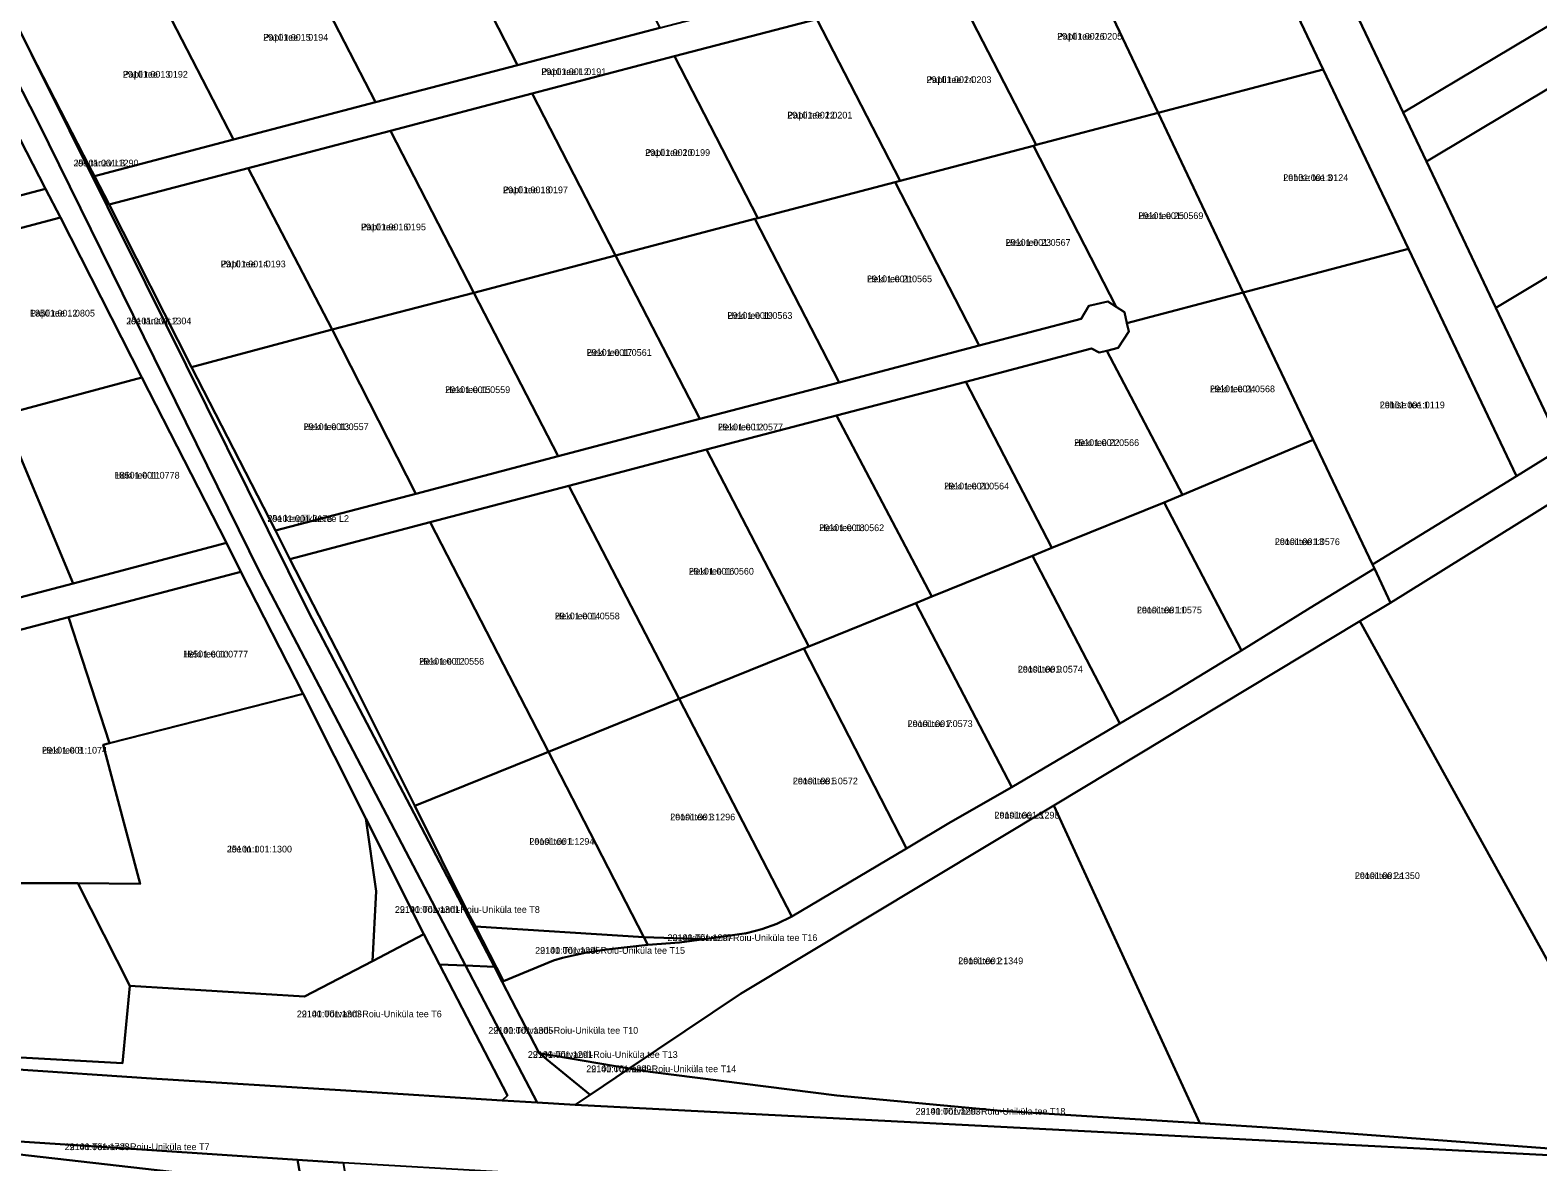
# Model space of a CAD drawing. Extents: x 660838 to 697091, y 6455678 to 6479886.
# Drawn here: x 664095.1 to 664431.6, y 6468197.9 to 6468450.3 of the extents above; entities that cross this region are included whole.
import ezdxf

# ---------------------------------------------------------------- set-up
doc = ezdxf.new("R2010")
doc.units = 0
for name, color, linetype in [('L_AADRESS', 7, 'Continuous'), ('PIIR', 7, 'Continuous'), ('TUNNUS', 7, 'Continuous')]:
    doc.layers.add(name, color=color, linetype=linetype)

msp = doc.modelspace()

# ---------------------------------------------------------------- linework, layer by layer
at = {"layer": 'PIIR'}
for points in [[(664313.61, 6468617.19), (664329.19, 6468584.39), (664334.36, 6468573.5), (664349.87, 6468540.83), (664365.38, 6468508.16), (664370.55, 6468497.27), (664386.06, 6468464.6), (664401.57, 6468431.93), (664406.74, 6468421.04), (664422.25, 6468388.37), (664437.07, 6468357.15), (664426.82, 6468350.79), (664402.72, 6468401.53), (664383.72, 6468441.55), (664365.17, 6468480.63), (664346.15, 6468520.69), (664326.53, 6468562.01), (664307.92, 6468601.21), (664288.66, 6468641.77)], [(664091.28, 6468218.5), (664122.2, 6468216.46), (664165.54, 6468213.74), (664200.48, 6468211.55), (664208.27, 6468211.09), (664216.77, 6468210.57), (664458.53, 6468198.06), (664579, 6468191.33), (664690.49, 6468185.61)], [(664729.07, 6468167.61), (664473.29, 6468181.55), (664464.58, 6468181.83), (664462.14, 6468181.96), (664413.82, 6468184.41), (664347.63, 6468187.75), (664236.55, 6468193.43), (664164.93, 6468197.64), (664154.73, 6468198.28), (664121.17, 6468200.49), (664090.44, 6468202.53)]]:
    msp.add_lwpolyline(points, dxfattribs=at)
for points in [[(664011.97, 6468594.44), (664010.85, 6468610.16), (664020.16, 6468591.48), (664045.52, 6468542.86), (664069.8, 6468495.5), (664072.61, 6468490.03), (664083.83, 6468468.15), (664091.12, 6468453.52), (664095.38, 6468444.97), (664120.83, 6468393.91), (664157.25, 6468320.55), (664198.71, 6468241.32), (664192.29, 6468241.62), (664146.38, 6468329.37), (664096.86, 6468429.82), (664045.92, 6468529.46), (664044.65, 6468529.2), (664044.72, 6468533.87), (664017.4, 6468586.35)], [(664406.74, 6468421.04), (664401.57, 6468431.93), (664442.44, 6468456.35), (664479.35, 6468478.41), (664519.73, 6468502.53), (664523.16, 6468504.58), (664566.08, 6468530.22), (664609.01, 6468555.87), (664651.92, 6468581.5), (664658.19, 6468571.28), (664613.54, 6468544.6), (664571.48, 6468519.47), (664529.41, 6468494.33), (664547.97, 6468463.93), (664565.51, 6468435.19), (664562.05, 6468433.18), (664544.54, 6468461.87), (664525.98, 6468492.28), (664485.63, 6468468.18), (664445.28, 6468444.07)], [(664061.69, 6468487.25), (664058.48, 6468493.66), (664040.86, 6468528.27), (664042.85, 6468528.78), (664044.65, 6468529.2), (664045.92, 6468529.46), (664096.86, 6468429.82), (664146.38, 6468329.37), (664192.29, 6468241.62), (664186.43, 6468241.89), (664182.99, 6468248.64), (664170.02, 6468274.46), (664156.03, 6468302.27), (664142.09, 6468329.5), (664138.93, 6468335.94), (664119.99, 6468372.84), (664101.86, 6468408.55), (664098.51, 6468414.91), (664082.82, 6468445.33), (664075.71, 6468459.37)], [(664398.73, 6468322.58), (664395.13, 6468330.21), (664394.74, 6468331.12), (664426.82, 6468350.79), (664437.07, 6468357.15), (664481.53, 6468384.67), (664521.71, 6468409.06), (664562.05, 6468433.18), (664565.51, 6468435.19), (664607.86, 6468459.86), (664650.34, 6468484.32), (664690.06, 6468507.49), (664700.43, 6468513.57), (664700.73, 6468512.97), (664584.64, 6468443.92), (664588.08, 6468438.22), (664559.82, 6468421.4), (664544.15, 6468411.97), (664487.89, 6468378.07)], [(664185.46, 6468478.38), (664217.17, 6468486.73), (664235.65, 6468450.87), (664203.9, 6468442.55)], [(664401.57, 6468431.93), (664386.06, 6468464.6), (664423.68, 6468487.09), (664442.44, 6468456.35)], [(664346.87, 6468431.87), (664328.13, 6468471.41), (664365.17, 6468480.63), (664383.72, 6468441.55)], [(664153.76, 6468470.03), (664185.46, 6468478.38), (664203.9, 6468442.55), (664172.21, 6468434.24)], [(664293.66, 6468467.54), (664297.73, 6468469.22), (664298.27, 6468468.99), (664301.79, 6468467.54), (664302.8, 6468465.1), (664303.48, 6468463.47), (664301.8, 6468459.42), (664297.73, 6468457.72), (664294.48, 6468459.06), (664270.67, 6468452.82), (664238.94, 6468444.5), (664207.18, 6468436.17), (664175.5, 6468427.87), (664143.75, 6468419.54), (664112.73, 6468411.41), (664109.42, 6468417.78), (664140.45, 6468425.92), (664172.21, 6468434.24), (664203.9, 6468442.55), (664235.65, 6468450.87), (664267.38, 6468459.19), (664292.77, 6468465.85)], [(664122.04, 6468461.69), (664153.76, 6468470.03), (664172.21, 6468434.24), (664140.45, 6468425.92)], [(664302.8, 6468465.1), (664328.13, 6468471.41), (664346.87, 6468431.87), (664319.63, 6468424.72), (664301.8, 6468459.42), (664303.48, 6468463.47)], [(664091.12, 6468453.52), (664122.04, 6468461.69), (664140.45, 6468425.92), (664109.42, 6468417.78), (664108.26, 6468419.99), (664095.38, 6468444.97)], [(664297.73, 6468457.72), (664301.8, 6468459.42), (664319.63, 6468424.72), (664319.03, 6468424.56), (664289.26, 6468416.74), (664270.67, 6468452.82), (664294.48, 6468459.06)], [(664238.94, 6468444.5), (664270.67, 6468452.82), (664289.26, 6468416.74), (664288.14, 6468416.45), (664257.52, 6468408.41)], [(664047.87, 6468442.82), (664071.93, 6468449.23), (664074.89, 6468442.69), (664082.82, 6468445.33), (664098.51, 6468414.91), (664064.26, 6468405.93)], [(664157.25, 6468320.55), (664120.83, 6468393.91), (664095.38, 6468444.97), (664108.26, 6468419.99), (664109.42, 6468417.78), (664112.73, 6468411.41), (664131.12, 6468375.17), (664149.86, 6468338.73), (664153.03, 6468332.3), (664165.97, 6468307.19), (664180.96, 6468277.24), (664192.82, 6468253.46), (664194.46, 6468250.34), (664200.77, 6468238.18), (664200.45, 6468238.01), (664198.71, 6468241.32)], [(664207.18, 6468436.17), (664238.94, 6468444.5), (664257.52, 6468408.41), (664256.84, 6468408.24), (664225.76, 6468400.06)], [(664422.25, 6468388.37), (664406.74, 6468421.04), (664445.28, 6468444.07), (664463.97, 6468413.44)], [(664365.86, 6468391.8), (664346.87, 6468431.87), (664383.72, 6468441.55), (664402.72, 6468401.53)], [(664175.5, 6468427.87), (664207.18, 6468436.17), (664225.76, 6468400.06), (664194.1, 6468391.73)], [(664319.63, 6468424.72), (664346.87, 6468431.87), (664365.86, 6468391.8), (664339.9, 6468384.98), (664339.35, 6468387.39), (664337.49, 6468388.61), (664319.03, 6468424.56)], [(664143.75, 6468419.54), (664175.5, 6468427.87), (664194.1, 6468391.73), (664162.54, 6468383.54)], [(664289.26, 6468416.74), (664319.03, 6468424.56), (664337.49, 6468388.61), (664335.65, 6468389.76), (664331.39, 6468388.82), (664329.65, 6468385.89), (664306.93, 6468379.95), (664288.14, 6468416.45)], [(664112.73, 6468411.41), (664143.75, 6468419.54), (664162.54, 6468383.54), (664131.12, 6468375.17)], [(664257.52, 6468408.41), (664288.14, 6468416.45), (664306.93, 6468379.95), (664275.69, 6468371.75), (664256.84, 6468408.24)], [(664098.51, 6468414.91), (664101.86, 6468408.55), (664070.12, 6468400.11), (664037.18, 6468391.48), (664004.69, 6468382.98), (663972.11, 6468374.47), (663939.71, 6468366), (663931.01, 6468363.73), (663930.12, 6468366.43), (663928.84, 6468370.43), (663935.15, 6468372.06), (663965.71, 6468380.05), (663998.2, 6468388.6), (664030.62, 6468397.11), (664064.26, 6468405.93)], [(664437.07, 6468357.15), (664422.25, 6468388.37), (664463.97, 6468413.44), (664481.53, 6468384.67)], [(664070.12, 6468400.11), (664101.86, 6468408.55), (664119.99, 6468372.84), (664088.98, 6468364.5), (664085.96, 6468363.69)], [(664225.76, 6468400.06), (664256.84, 6468408.24), (664275.69, 6468371.75), (664244.54, 6468363.58)], [(664194.1, 6468391.73), (664225.76, 6468400.06), (664244.54, 6468363.58), (664212.93, 6468355.27)], [(664394.74, 6468331.12), (664381.49, 6468358.94), (664365.86, 6468391.8), (664402.72, 6468401.53), (664426.82, 6468350.79)], [(664162.54, 6468383.54), (664194.1, 6468391.73), (664212.93, 6468355.27), (664181.16, 6468346.92)], [(664339.9, 6468384.98), (664365.86, 6468391.8), (664381.49, 6468358.94), (664352.28, 6468346.65), (664335.39, 6468378.8), (664337.97, 6468379.42), (664340.32, 6468383.1)], [(664331.39, 6468388.82), (664335.65, 6468389.76), (664337.49, 6468388.61), (664339.35, 6468387.39), (664339.9, 6468384.98), (664340.32, 6468383.1), (664337.97, 6468379.42), (664335.39, 6468378.8), (664333.68, 6468378.44), (664331.98, 6468379.3), (664303.94, 6468371.9), (664275.06, 6468364.35), (664246.09, 6468356.75), (664215.36, 6468348.7), (664184.41, 6468340.56), (664153.03, 6468332.3), (664149.86, 6468338.73), (664181.16, 6468346.92), (664212.93, 6468355.27), (664244.54, 6468363.58), (664275.69, 6468371.75), (664306.93, 6468379.95), (664329.65, 6468385.89)], [(664131.12, 6468375.17), (664162.54, 6468383.54), (664181.16, 6468346.92), (664149.86, 6468338.73)], [(664303.94, 6468371.9), (664331.98, 6468379.3), (664333.68, 6468378.44), (664335.39, 6468378.8), (664352.28, 6468346.65), (664348.18, 6468344.97), (664323.12, 6468334.82)], [(664487.89, 6468378.07), (664579, 6468191.33), (664458.53, 6468198.06), (664458.37, 6468198.35), (664457.98, 6468199.04), (664391.9, 6468318.48), (664398.73, 6468322.58)], [(664088.98, 6468364.5), (664119.99, 6468372.84), (664138.93, 6468335.94), (664104.7, 6468326.9)], [(664275.06, 6468364.35), (664303.94, 6468371.9), (664323.12, 6468334.82), (664318.82, 6468333.05), (664296.32, 6468323.97)], [(664056.43, 6468355.76), (664085.96, 6468363.69), (664088.98, 6468364.5), (664104.7, 6468326.9), (664071.43, 6468318.15)], [(664246.09, 6468356.75), (664275.06, 6468364.35), (664296.32, 6468323.97), (664292.78, 6468322.5), (664268.9, 6468312.84)], [(664352.28, 6468346.65), (664381.49, 6468358.94), (664394.74, 6468331.12), (664395.13, 6468330.21), (664380.78, 6468321.45), (664365.44, 6468311.96), (664348.18, 6468344.97)], [(664215.36, 6468348.7), (664246.09, 6468356.75), (664268.9, 6468312.84), (664267.76, 6468312.36), (664239.98, 6468301.13)], [(664184.41, 6468340.56), (664215.36, 6468348.7), (664239.98, 6468301.13), (664210.81, 6468289.33)], [(664323.12, 6468334.82), (664348.18, 6468344.97), (664365.44, 6468311.96), (664349.44, 6468302.21), (664338.32, 6468295.65), (664318.82, 6468333.05)], [(664153.03, 6468332.3), (664184.41, 6468340.56), (664210.81, 6468289.33), (664180.96, 6468277.24), (664165.97, 6468307.19)], [(664138.93, 6468335.94), (664142.09, 6468329.5), (664103.67, 6468319.4), (664075.84, 6468312.07), (664047.71, 6468304.7), (664018.32, 6468296.96), (663982.59, 6468287.6), (663964.77, 6468282.8), (663964.11, 6468284.71), (663962.55, 6468289.49), (663972.93, 6468292.22), (664005.47, 6468300.79), (664038.5, 6468309.59), (664071.43, 6468318.15), (664104.7, 6468326.9)], [(664296.32, 6468323.97), (664318.82, 6468333.05), (664338.32, 6468295.65), (664314.17, 6468281.47), (664292.78, 6468322.5)], [(664103.67, 6468319.4), (664142.09, 6468329.5), (664156.03, 6468302.27), (664112.78, 6468291.23)], [(664380.78, 6468321.45), (664395.13, 6468330.21), (664398.73, 6468322.58), (664391.9, 6468318.48), (664323.58, 6468277.38), (664253.65, 6468235.35), (664228.83, 6468218.67), (664208.74, 6468222.11), (664200.45, 6468238.01), (664200.77, 6468238.18), (664211.94, 6468242.79), (664213.9, 6468243.39), (664219.33, 6468244.54), (664223.71, 6468245.23), (664232.96, 6468246.28), (664240, 6468246.81), (664245.5, 6468247.56), (664255, 6468248.85), (664258.39, 6468249.78), (664261.78, 6468250.92), (664265.1, 6468252.62), (664290.71, 6468267.78), (664300.51, 6468273.6), (664314.17, 6468281.47), (664338.32, 6468295.65), (664349.44, 6468302.21), (664365.44, 6468311.96)], [(664268.9, 6468312.84), (664292.78, 6468322.5), (664314.17, 6468281.47), (664300.51, 6468273.6), (664290.71, 6468267.78), (664267.76, 6468312.36)], [(664075.84, 6468312.07), (664103.67, 6468319.4), (664112.78, 6468291.23), (664111.41, 6468290.88), (664119.66, 6468259.88), (664105.73, 6468259.99), (664090.17, 6468260.05)], [(664323.58, 6468277.38), (664391.9, 6468318.48), (664457.98, 6468199.04), (664374.67, 6468205.31), (664356.17, 6468206.5)], [(664239.98, 6468301.13), (664267.76, 6468312.36), (664290.71, 6468267.78), (664265.1, 6468252.62)], [(664112.78, 6468291.23), (664156.03, 6468302.27), (664170.02, 6468274.46), (664172.33, 6468258.27), (664171.5, 6468242.59), (664156.34, 6468234.74), (664117.34, 6468237.15), (664105.73, 6468259.99), (664119.66, 6468259.88), (664111.41, 6468290.88)], [(664210.81, 6468289.33), (664239.98, 6468301.13), (664265.1, 6468252.62), (664261.78, 6468250.92), (664258.39, 6468249.78), (664255, 6468248.85), (664245.5, 6468247.56), (664232.08, 6468247.94)], [(664117.34, 6468237.15), (664115.71, 6468219.88), (664059.46, 6468222.99), (663965.92, 6468232.47), (663944.79, 6468278.74), (663964.11, 6468284.71), (663964.77, 6468282.8), (663982.59, 6468287.6), (663992.24, 6468260.2), (664029.61, 6468260.17), (664060.31, 6468260.11), (664084.21, 6468260.09), (664090.17, 6468260.05), (664105.73, 6468259.99)], [(664194.46, 6468250.34), (664192.82, 6468253.46), (664180.96, 6468277.24), (664210.81, 6468289.33), (664232.08, 6468247.94)], [(664228.83, 6468218.67), (664253.65, 6468235.35), (664323.58, 6468277.38), (664356.17, 6468206.5), (664311.77, 6468209.25), (664275.11, 6468212.64), (664233.46, 6468217.91)], [(664172.33, 6468258.27), (664170.02, 6468274.46), (664182.99, 6468248.64), (664171.5, 6468242.59)], [(664200.77, 6468238.18), (664194.46, 6468250.34), (664232.08, 6468247.94), (664232.96, 6468246.28), (664223.71, 6468245.23), (664219.33, 6468244.54), (664213.9, 6468243.39), (664211.94, 6468242.79)], [(663965.79, 6468231.38), (663965.92, 6468232.47), (664059.46, 6468222.99), (664115.71, 6468219.88), (664117.34, 6468237.15), (664156.34, 6468234.74), (664171.5, 6468242.59), (664182.99, 6468248.64), (664186.43, 6468241.89), (664201.65, 6468212.63), (664200.48, 6468211.55), (664165.54, 6468213.74), (664122.2, 6468216.46), (664091.28, 6468218.5), (664074.07, 6468219.81), (664052.27, 6468221.67), (664031.71, 6468223.7), (664010.87, 6468226), (663986.88, 6468228.81)], [(664232.96, 6468246.28), (664232.08, 6468247.94), (664245.5, 6468247.56), (664240, 6468246.81)], [(664201.65, 6468212.63), (664186.43, 6468241.89), (664192.29, 6468241.62), (664208.27, 6468211.09), (664200.48, 6468211.55)], [(664208.27, 6468211.09), (664192.29, 6468241.62), (664198.71, 6468241.32), (664200.45, 6468238.01), (664208.74, 6468222.11), (664220.08, 6468212.77), (664216.77, 6468210.57)], [(664220.08, 6468212.77), (664208.74, 6468222.11), (664228.83, 6468218.67)], [(664458.53, 6468198.06), (664216.77, 6468210.57), (664220.08, 6468212.77), (664228.83, 6468218.67), (664233.46, 6468217.91), (664275.11, 6468212.64), (664311.77, 6468209.25), (664356.17, 6468206.5), (664374.67, 6468205.31), (664457.98, 6468199.04), (664458.37, 6468198.35)], [(664148.88, 6468193.07), (663995.49, 6468210.56), (663995.18, 6468211.75), (664009.18, 6468210.01), (664029.84, 6468207.79), (664050.89, 6468205.83), (664072.71, 6468203.97), (664090.44, 6468202.53), (664121.17, 6468200.49), (664154.73, 6468198.28), (664156.38, 6468189.18)], [(664057.12, 6467961.27), (663995.49, 6468210.56), (664148.88, 6468193.07), (664156.38, 6468189.18), (664156.84, 6468186.18), (664188.82, 6468093.34), (664212.9, 6468021.9), (664222.24, 6467993.73), (664224.85, 6467985.32)], [(664171.04, 6468175.63), (664156.38, 6468189.18), (664154.73, 6468198.28), (664164.93, 6468197.64), (664166.48, 6468188.79)]]:
    msp.add_lwpolyline(points, close=True, dxfattribs=at)

# ---------------------------------------------------------------- texts
at = {"layer": 'L_AADRESS'}
for s, p in [('Papli tee 15', (664147.12, 6468447.98)), ('Papli tee 26', (664324.33, 6468448.21)), ('Papli tee 13', (664115.79, 6468439.74)), ('Papli tee L2', (664209.18, 6468440.32)), ('Papli tee 24', (664295.15, 6468438.54)), ('Papli tee 22', (664264.1, 6468430.62)), ('Papli tee 20', (664232.35, 6468422.28)), ('Jõe tänav L3', (664104.78, 6468419.93)), ('Papli tee 18', (664200.63, 6468413.95)), ('Lehise tee 3', (664374.79, 6468416.68)), ('Heki tee 25', (664342.45, 6468408.18)), ('Papli tee 16', (664168.93, 6468405.67)), ('Heki tee 23', (664312.82, 6468402.21)), ('Papli tee 14', (664137.63, 6468397.42)), ('Heki tee 21', (664281.89, 6468394.09)), ('Papli tee 12', (664095.05, 6468386.44)), ('Jõe tänav L2', (664116.57, 6468384.7)), ('Heki tee 19', (664250.72, 6468385.92)), ('Heki tee 17', (664219.32, 6468377.66)), ('Heki tee 15', (664187.73, 6468369.36)), ('Heki tee 24', (664358.44, 6468369.55)), ('Lehise tee 1', (664396.34, 6468365.97)), ('Heki tee 13', (664156.14, 6468361.1)), ('Heki tee L2', (664248.62, 6468361.03)), ('Heki tee 22', (664328.11, 6468357.56)), ('Heki tee 11', (664113.95, 6468350.28)), ('Heki tee 20', (664299.09, 6468347.86)), ('Jõe kergliiklustee L2', (664148.08, 6468340.62)), ('Heki tee 18', (664271.21, 6468338.56)), ('Loosi tee 13', (664372.92, 6468335.45)), ('Heki tee 16', (664242.13, 6468328.86)), ('Loosi tee 11', (664342.13, 6468320.21)), ('Heki tee 14', (664212.19, 6468318.88)), ('Heki tee 10', (664129.24, 6468310.37)), ('Heki tee 12', (664181.92, 6468308.77)), ('Loosi tee 9', (664315.55, 6468307.01)), ('Loosi tee 7', (664290.96, 6468294.85)), ('Heki tee 8', (664097.75, 6468288.93)), ('Loosi tee 5', (664265.34, 6468282.07)), ('Loosi tee 3', (664237.96, 6468274.04)), ('Loosi tee L3', (664310.33, 6468274.44)), ('Jõe tn 1', (664139.03, 6468266.87)), ('Loosi tee 1', (664206.52, 6468268.58)), ('Loosi tee 2a', (664390.78, 6468260.95)), ('22140 Tõrvandi-Roiu-Uniküla tee T8', (664176.51, 6468253.39)), ('22140 Tõrvandi-Roiu-Uniküla tee T16', (664237.36, 6468247.11)), ('22140 Tõrvandi-Roiu-Uniküla tee T15', (664207.81, 6468244.26)), ('Loosi tee 2', (664302.24, 6468241.94)), ('22140 Tõrvandi-Roiu-Uniküla tee T6', (664154.62, 6468230.1)), ('22140 Tõrvandi-Roiu-Uniküla tee T10', (664197.35, 6468226.42)), ('22140 Tõrvandi-Roiu-Uniküla tee T13', (664206.18, 6468221.04)), ('22140 Tõrvandi-Roiu-Uniküla tee T14', (664219.22, 6468217.85)), ('22140 Tõrvandi-Roiu-Uniküla tee T18', (664292.72, 6468208.37)), ('22140 Tõrvandi-Roiu-Uniküla tee T7', (664102.79, 6468200.46))]:
    msp.add_text(s, height=1.5, dxfattribs=at).set_placement(p)
at = {"layer": 'TUNNUS'}
for s, p in [('29101:001:0194', (664147.12, 6468447.98)), ('29101:001:0205', (664324.33, 6468448.21)), ('29101:001:0192', (664115.79, 6468439.74)), ('29101:001:0191', (664209.18, 6468440.32)), ('29101:001:0203', (664295.15, 6468438.54)), ('29101:001:0201', (664264.1, 6468430.62)), ('29101:001:0199', (664232.35, 6468422.28)), ('29101:001:1290', (664104.78, 6468419.93)), ('29101:001:0197', (664200.63, 6468413.95)), ('29101:001:0124', (664374.79, 6468416.68)), ('29101:001:0569', (664342.45, 6468408.18)), ('29101:001:0195', (664168.93, 6468405.67)), ('29101:001:0567', (664312.82, 6468402.21)), ('29101:001:0193', (664137.63, 6468397.42)), ('29101:001:0565', (664281.89, 6468394.09)), ('18501:001:0805', (664095.05, 6468386.44)), ('29101:001:1304', (664116.57, 6468384.7)), ('29101:001:0563', (664250.72, 6468385.92)), ('29101:001:0561', (664219.32, 6468377.66)), ('29101:001:0559', (664187.73, 6468369.36)), ('29101:001:0568', (664358.44, 6468369.55)), ('29101:001:0119', (664396.34, 6468365.97)), ('29101:001:0557', (664156.14, 6468361.1)), ('29101:001:0577', (664248.62, 6468361.03)), ('29101:001:0566', (664328.11, 6468357.56)), ('18501:001:0778', (664113.95, 6468350.28)), ('29101:001:0564', (664299.09, 6468347.86)), ('29101:001:0175', (664148.08, 6468340.62)), ('29101:001:0562', (664271.21, 6468338.56)), ('29101:001:0576', (664372.92, 6468335.45)), ('29101:001:0560', (664242.13, 6468328.86)), ('29101:001:0575', (664342.13, 6468320.21)), ('29101:001:0558', (664212.19, 6468318.88)), ('18501:001:0777', (664129.24, 6468310.37)), ('29101:001:0556', (664181.92, 6468308.77)), ('29101:001:0574', (664315.55, 6468307.01)), ('29101:001:0573', (664290.96, 6468294.85)), ('29101:001:1074', (664097.75, 6468288.93)), ('29101:001:0572', (664265.34, 6468282.07)), ('29101:001:1296', (664237.96, 6468274.04)), ('29101:001:1298', (664310.33, 6468274.44)), ('29101:001:1300', (664139.03, 6468266.87)), ('29101:001:1294', (664206.52, 6468268.58)), ('29101:001:1350', (664390.78, 6468260.95)), ('29101:001:1301', (664176.51, 6468253.39)), ('29101:001:1297', (664237.36, 6468247.11)), ('29101:001:1295', (664207.81, 6468244.26)), ('29101:001:1349', (664302.24, 6468241.94)), ('29101:001:1303', (664154.62, 6468230.1)), ('29101:001:1305', (664197.35, 6468226.42)), ('29101:001:1291', (664206.18, 6468221.04)), ('29101:001:1299', (664219.22, 6468217.85)), ('29101:001:1293', (664292.72, 6468208.37)), ('29101:001:1728', (664102.79, 6468200.46))]:
    msp.add_text(s, height=1.5, dxfattribs=at).set_placement(p)

doc.saveas('drawing.dxf')
